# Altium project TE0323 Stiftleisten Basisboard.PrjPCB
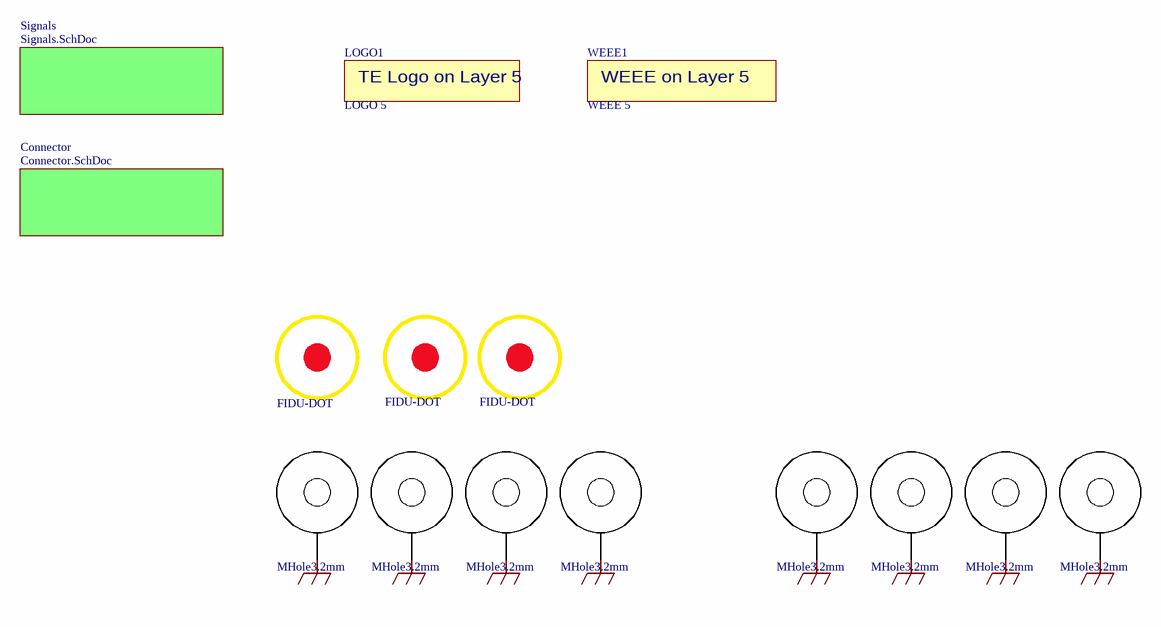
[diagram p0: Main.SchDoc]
3 sheets, 54 parts. Net scope: global (net labels, ports and power ports of the same name join across sheets).
Board file: TE0323.PcbDoc
Sheets:
  Main.SchDoc
    Connector = Connector.SchDoc
    Signals = Signals.SchDoc

## Sheet Main.SchDoc: Header Baseboard - TE0320 Module
size A4; Organization: Trenz Electronic GmbH; DocumentNumber: TE0323; Revision: 00; SheetNumber: 1; SheetTotal: 3; Date: 2008-07-08

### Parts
H1  MHole3.2mm  [MHole3_2mm]  (no BOM)
H2  MHole3.2mm  [MHole3_2mm]  (no BOM)
H3  MHole3.2mm  [MHole3_2mm]  (no BOM)
H4  MHole3.2mm  [MHole3_2mm]  (no BOM)
H5  MHole3.2mm  [MHole3_2mm]  (no BOM)
H6  MHole3.2mm  [MHole3_2mm]  (no BOM)
H7  MHole3.2mm  [MHole3_2mm]  (no BOM)
H8  MHole3.2mm  [MHole3_2mm]  (no BOM)
LOGO1  LOGO 5  [Logo 5]  (no BOM)
PM1  FIDU-DOT  [FIDU-DOT]
PM2  FIDU-DOT  [FIDU-DOT]
PM3  FIDU-DOT  [FIDU-DOT]
WEEE1  WEEE 5  [WEEE5_10_25mm]  (no BOM)

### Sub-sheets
Connector = Connector.SchDoc: no entries
Signals = Signals.SchDoc: no entries

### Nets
FGND: H1.1 H2.1 H3.1 H4.1 H5.1 H6.1 H7.1 H8.1

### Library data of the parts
H1-H8 = 22898: AN: 22898
LOGO1 = 22903: AN: 22903
PM1-PM3 = 22906: AN: 22906
WEEE1 = 23537: WEEE 5 (10.25mm); AN: 23537

## Sheet Connector.SchDoc: Header Baseboard - Headers
size A4; Organization: Trenz Electronic GmbH; DocumentNumber: TE0323; Revision: 00; SheetNumber: 3; SheetTotal: 3; Date: 2008-07-08
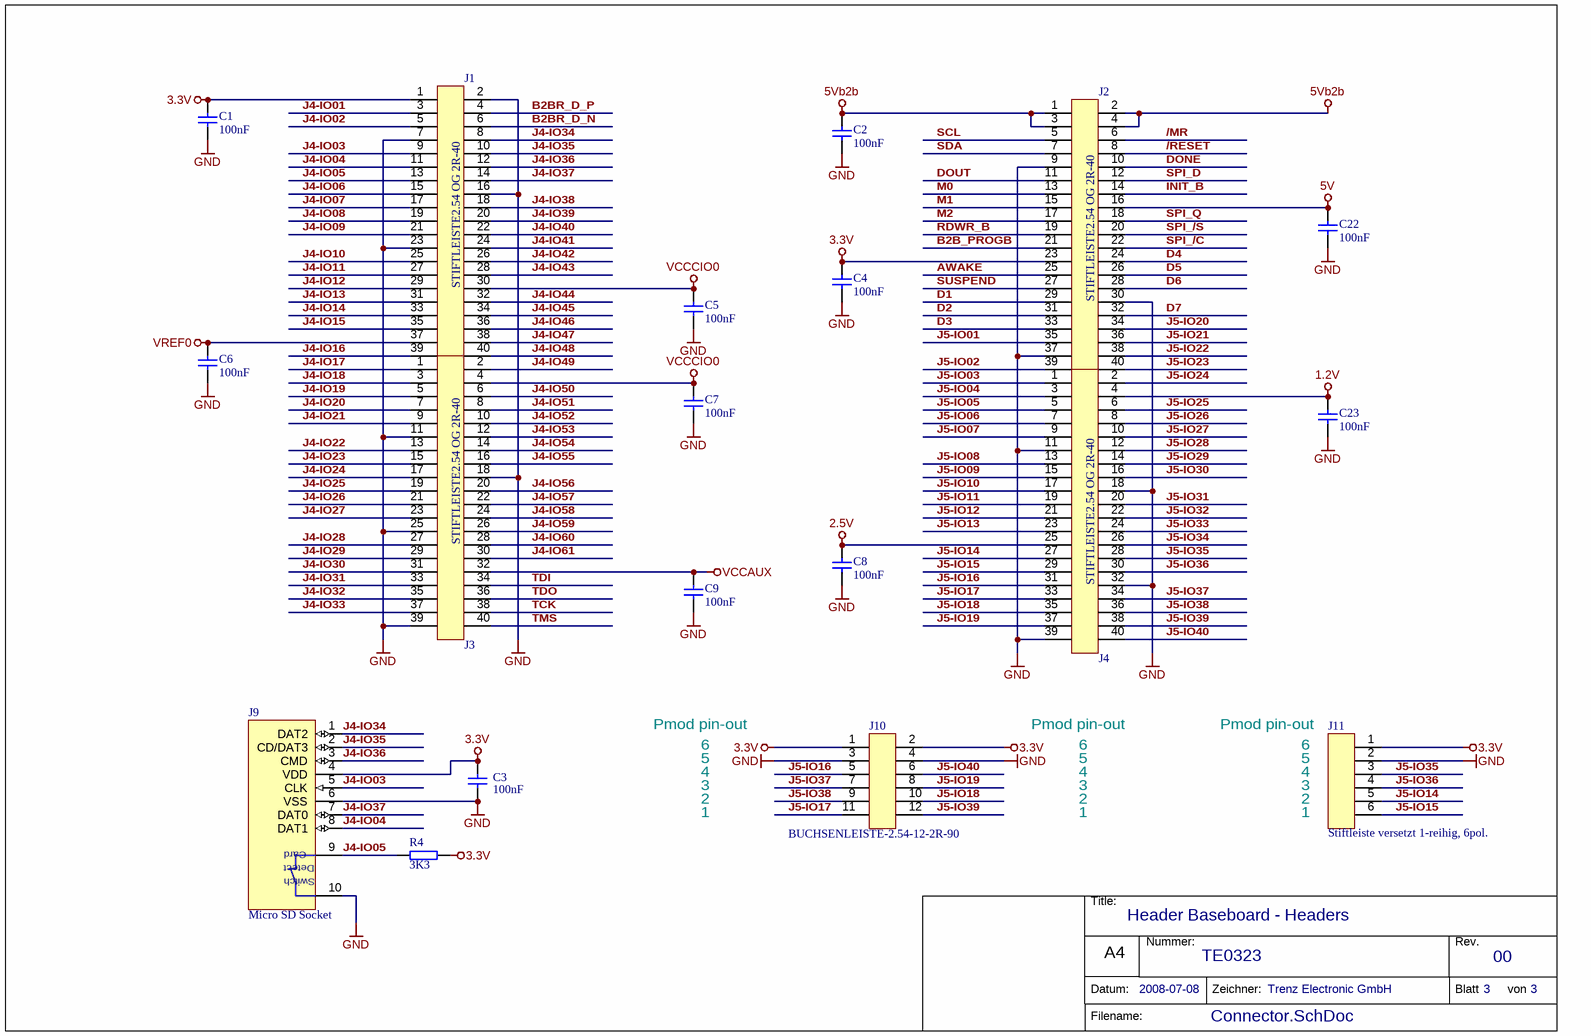
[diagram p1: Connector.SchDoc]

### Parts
C1  100nF  [CAPC1608N]
C2  100nF  [CAPC1608N]
C3  100nF  [CAPC1608N]
C4  100nF  [CAPC1608N]
C5  100nF  [CAPC1608N]
C6  100nF  [CAPC1608N]
C7  100nF  [CAPC1608N]
C8  100nF  [CAPC1608N]
C9  100nF  [CAPC1608N]
C22  100nF  [CAPC1608N]
C23  100nF  [CAPC1608N]
J1  STIFTLEISTE2.54 OG 2R-40  [STIFTLEISTE2_54 OG 2R-40]
J2  STIFTLEISTE2.54 OG 2R-40  [STIFTLEISTE2_54 OG 2R-40]
J3  STIFTLEISTE2.54 OG 2R-40  [STIFTLEISTE2_54 OG 2R-40]
J4  STIFTLEISTE2.54 OG 2R-40  [STIFTLEISTE2_54 OG 2R-40]
J9  Micro SD Socket  [112A-TXAR-R01]
J10  BUCHSENLEISTE-2.54-12-2R-90  [BUCHSENLEISTE-2.54-12-2R-90]
J11  Stiftleiste versetzt 1-reihig, 6pol.  [STIFTLEISTE2_54 OG 1R-6V]
R4  3K3  [RESC1609N]

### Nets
1.2V: C23.1 J4.4
2.5V: C8.1 J4.25
3.3V: C1.1 C3.1 C4.1 J1.1 J2.23 J9.4(VDD) J10.1 J10.2 J11.1 R4.2
5V: C22.1 J2.16
5Vb2b: C2.1 J2.1 J2.2 J2.3 J2.4
GND: C1.2 C2.2 C3.2 C4.2 C5.2 C6.2 C7.2 C8.2 C9.2 C22.2 C23.2 J1.2 J1.7 J1.16 J1.23 J2.9 J2.30 J2.37 J3.11 J3.18 J3.25 J3.39 J4.11 J4.18 J4.32 J4.39 J9.6(VSS) J9.10 J10.3 J10.4 J11.2
VCCAUX: C9.1 J3.32
VCCCIO0: C5.1 C7.1 J1.30 J3.4
VREF0: C6.1 J1.37
/MR: J2.6
/RESET: J2.8
AWAKE: J2.25
B2B_PROGB: J2.21
B2BR_D_N: J1.6
B2BR_D_P: J1.4
D1: J2.29
D2: J2.31
D3: J2.33
D4: J2.24
D5: J2.26
D6: J2.28
D7: J2.32
DONE: J2.10
DOUT: J2.11
INIT_B: J2.14
J4-IO01: J1.3
J4-IO02: J1.5
J4-IO03: J1.9 J9.5(CLK)
J4-IO04: J1.11 J9.8(DAT1)
J4-IO05: J1.13 J9.9 R4.1
J4-IO06: J1.15
J4-IO07: J1.17
J4-IO08: J1.19
J4-IO09: J1.21
J4-IO10: J1.25
J4-IO11: J1.27
J4-IO12: J1.29
J4-IO13: J1.31
J4-IO14: J1.33
J4-IO15: J1.35
J4-IO16: J1.39
J4-IO17: J3.1
J4-IO18: J3.3
J4-IO19: J3.5
J4-IO20: J3.7
J4-IO21: J3.9
J4-IO22: J3.13
J4-IO23: J3.15
J4-IO24: J3.17
J4-IO25: J3.19
J4-IO26: J3.21
J4-IO27: J3.23
J4-IO28: J3.27
J4-IO29: J3.29
J4-IO30: J3.31
J4-IO31: J3.33
J4-IO32: J3.35
J4-IO33: J3.37
J4-IO34: J1.8 J9.1(DAT2)
J4-IO35: J1.10 J9.2(CD/DAT3)
J4-IO36: J1.12 J9.3(CMD)
J4-IO37: J1.14 J9.7(DAT0)
J4-IO38: J1.18
J4-IO39: J1.20
J4-IO40: J1.22
J4-IO41: J1.24
J4-IO42: J1.26
J4-IO43: J1.28
J4-IO44: J1.32
J4-IO45: J1.34
J4-IO46: J1.36
J4-IO47: J1.38
J4-IO48: J1.40
J4-IO49: J3.2
J4-IO50: J3.6
J4-IO51: J3.8
J4-IO52: J3.10
J4-IO53: J3.12
J4-IO54: J3.14
J4-IO55: J3.16
J4-IO56: J3.20
J4-IO57: J3.22
J4-IO58: J3.24
J4-IO59: J3.26
J4-IO60: J3.28
J4-IO61: J3.30
J5-IO01: J2.35
J5-IO02: J2.39
J5-IO03: J4.1
J5-IO04: J4.3
J5-IO05: J4.5
J5-IO06: J4.7
J5-IO07: J4.9
J5-IO08: J4.13
J5-IO09: J4.15
J5-IO10: J4.17
J5-IO11: J4.19
J5-IO12: J4.21
J5-IO13: J4.23
J5-IO14: J4.27 J11.5
J5-IO15: J4.29 J11.6
J5-IO16: J4.31 J10.5
J5-IO17: J4.33 J10.11
J5-IO18: J4.35 J10.10
J5-IO19: J4.37 J10.8
J5-IO20: J2.34
J5-IO21: J2.36
J5-IO22: J2.38
J5-IO23: J2.40
J5-IO24: J4.2
J5-IO25: J4.6
J5-IO26: J4.8
J5-IO27: J4.10
J5-IO28: J4.12
J5-IO29: J4.14
J5-IO30: J4.16
J5-IO31: J4.20
J5-IO32: J4.22
J5-IO33: J4.24
J5-IO34: J4.26
J5-IO35: J4.28 J11.3
J5-IO36: J4.30 J11.4
J5-IO37: J4.34 J10.7
J5-IO38: J4.36 J10.9
J5-IO39: J4.38 J10.12
J5-IO40: J4.40 J10.6
M0: J2.13
M1: J2.15
M2: J2.17
RDWR_B: J2.19
SCL: J2.5
SDA: J2.7
SPI_/C: J2.22
SPI_/S: J2.20
SPI_D: J2.12
SPI_Q: J2.18
SUSPEND: J2.27
TCK: J3.38
TDI: J3.34
TDO: J3.36
TMS: J3.40

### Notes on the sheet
- Pmod pin-out
- 3
- 4
- 5
- 6
- (near J11) Pmod pin-out
- (near J11) 3
- (near J11) 4
- (near J11) 5
- (near J11) 6
- 1
- 2
- (near J11) 1
- (near J11) 2

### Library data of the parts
C1-C9 C22 C23 = 21382: KON 100nF 50V X7R SMD; AN: 21382; Value: 100n; Param 4: SMT
J1-J4 = 22320: Stiftleiste gerade 2-reihig, 40pol; AN: 22320; Trenz-Stock: Yes
J9 = 23193: AN: 23193; Param 4: SMT; Trenz-Stock: Yes
J10 = 23185: Buchsenleiste 2-reihig, 12pol 90°; AN: 23185; Trenz-Stock: Yes
J11 = 22911: AN: 22911; Trenz-Stock: Yes
R4 = 22433: WID SMD 3K3 1% 0,1W; AN: 22433; Value: 3.3K; Param 4: SMT

## Sheet Signals.SchDoc: Header Baseboard - TE0320 Module
size A4; Organization: Trenz Electronic GmbH; DocumentNumber: TE0323; Revision: 00; SheetNumber: 2; SheetTotal: 3; Date: 2008-07-08
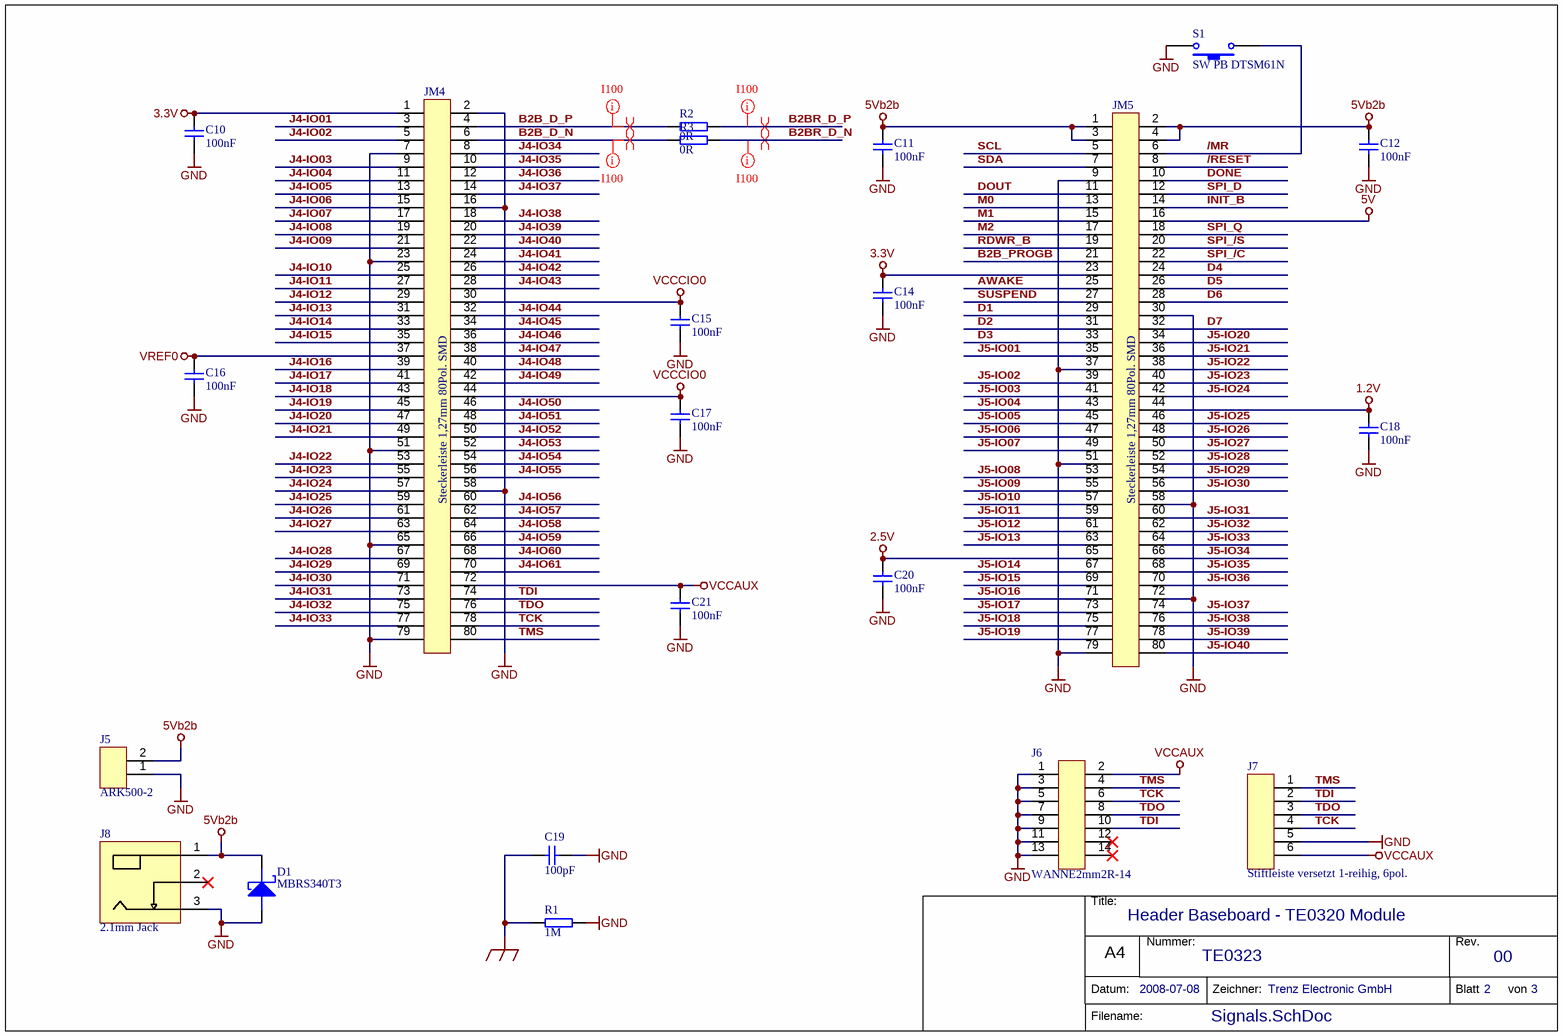
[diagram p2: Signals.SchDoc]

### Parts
C10  100nF  [CAPC1608N]
C11  100nF  [CAPC1608N]
C12  100nF  [CAPC1608N]
C14  100nF  [CAPC1608N]
C15  100nF  [CAPC1608N]
C16  100nF  [CAPC1608N]
C17  100nF  [CAPC1608N]
C18  100nF  [CAPC1608N]
C19  100pF  [CAPC3216N]
C20  100nF  [CAPC1608N]
C21  100nF  [CAPC1608N]
D1  MBRS340T3  [MBRS340T3]
J5  ARK500-2  [ARK500-2]
J6  WANNE2mm2R-14  [WANNE2mm2R-14]
J7  Stiftleiste versetzt 1-reihig, 6pol.  [STIFTLEISTE2_54 OG 1R-6V]
J8  2.1mm Jack  [WS-DC001]
JM4  Steckerleiste 1,27mm 80Pol. SMD  [6110-080-00-10]
JM5  Steckerleiste 1,27mm 80Pol. SMD  [6110-080-00-10]
R1  1M  [RESC3216N]
R2  0R  [RESC1609N]
R3  0R  [RESC1609N]
S1  SW PB DTSM61N  [DTSM61N]

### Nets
1.2V: C18.1 JM5.44
2.5V: C20.1 JM5.65
3.3V: C10.1 C14.1 JM4.1 JM5.23
5V: JM5.16
5Vb2b: C11.1 C12.1 D1.1(CATHODE) J5.2 J8.1 JM5.1 JM5.2 JM5.3 JM5.4
FGND: C19.1 R1.1
GND: C10.2 C11.2 C12.2 C14.2 C15.2 C16.2 C17.2 C18.2 C19.2 C20.2 C21.2 D1.2(ANODE) J5.1 J6.1 J6.3 J6.5 J6.7 J6.9 J6.11 J6.13 J7.5 J8.3 JM4.2 JM4.7 JM4.16 JM4.23 JM4.51 JM4.58 JM4.65 JM4.79 JM5.9 JM5.30 JM5.37 JM5.51 JM5.58 JM5.72 JM5.79 R1.2 S1.2
VCCAUX: C21.1 J6.2 J7.6 JM4.72
VCCCIO0: C15.1 C17.1 JM4.30 JM4.44
VREF0: C16.1 JM4.37
/MR: JM5.6 S1.1
/RESET: JM5.8
AWAKE: JM5.25
B2B_D_N: JM4.6 R3.1
B2B_D_P: JM4.4 R2.1
B2B_PROGB: JM5.21
B2BR_D_N: R3.2
B2BR_D_P: R2.2
D1: JM5.29
D2: JM5.31
D3: JM5.33
D4: JM5.24
D5: JM5.26
D6: JM5.28
D7: JM5.32
DONE: JM5.10
DOUT: JM5.11
INIT_B: JM5.14
J4-IO01: JM4.3
J4-IO02: JM4.5
J4-IO03: JM4.9
J4-IO04: JM4.11
J4-IO05: JM4.13
J4-IO06: JM4.15
J4-IO07: JM4.17
J4-IO08: JM4.19
J4-IO09: JM4.21
J4-IO10: JM4.25
J4-IO11: JM4.27
J4-IO12: JM4.29
J4-IO13: JM4.31
J4-IO14: JM4.33
J4-IO15: JM4.35
J4-IO16: JM4.39
J4-IO17: JM4.41
J4-IO18: JM4.43
J4-IO19: JM4.45
J4-IO20: JM4.47
J4-IO21: JM4.49
J4-IO22: JM4.53
J4-IO23: JM4.55
J4-IO24: JM4.57
J4-IO25: JM4.59
J4-IO26: JM4.61
J4-IO27: JM4.63
J4-IO28: JM4.67
J4-IO29: JM4.69
J4-IO30: JM4.71
J4-IO31: JM4.73
J4-IO32: JM4.75
J4-IO33: JM4.77
J4-IO34: JM4.8
J4-IO35: JM4.10
J4-IO36: JM4.12
J4-IO37: JM4.14
J4-IO38: JM4.18
J4-IO39: JM4.20
J4-IO40: JM4.22
J4-IO41: JM4.24
J4-IO42: JM4.26
J4-IO43: JM4.28
J4-IO44: JM4.32
J4-IO45: JM4.34
J4-IO46: JM4.36
J4-IO47: JM4.38
J4-IO48: JM4.40
J4-IO49: JM4.42
J4-IO50: JM4.46
J4-IO51: JM4.48
J4-IO52: JM4.50
J4-IO53: JM4.52
J4-IO54: JM4.54
J4-IO55: JM4.56
J4-IO56: JM4.60
J4-IO57: JM4.62
J4-IO58: JM4.64
J4-IO59: JM4.66
J4-IO60: JM4.68
J4-IO61: JM4.70
J5-IO01: JM5.35
J5-IO02: JM5.39
J5-IO03: JM5.41
J5-IO04: JM5.43
J5-IO05: JM5.45
J5-IO06: JM5.47
J5-IO07: JM5.49
J5-IO08: JM5.53
J5-IO09: JM5.55
J5-IO10: JM5.57
J5-IO11: JM5.59
J5-IO12: JM5.61
J5-IO13: JM5.63
J5-IO14: JM5.67
J5-IO15: JM5.69
J5-IO16: JM5.71
J5-IO17: JM5.73
J5-IO18: JM5.75
J5-IO19: JM5.77
J5-IO20: JM5.34
J5-IO21: JM5.36
J5-IO22: JM5.38
J5-IO23: JM5.40
J5-IO24: JM5.42
J5-IO25: JM5.46
J5-IO26: JM5.48
J5-IO27: JM5.50
J5-IO28: JM5.52
J5-IO29: JM5.54
J5-IO30: JM5.56
J5-IO31: JM5.60
J5-IO32: JM5.62
J5-IO33: JM5.64
J5-IO34: JM5.66
J5-IO35: JM5.68
J5-IO36: JM5.70
J5-IO37: JM5.74
J5-IO38: JM5.76
J5-IO39: JM5.78
J5-IO40: JM5.80
M0: JM5.13
M1: JM5.15
M2: JM5.17
RDWR_B: JM5.19
SCL: JM5.5
SDA: JM5.7
SPI_/C: JM5.22
SPI_/S: JM5.20
SPI_D: JM5.12
SPI_Q: JM5.18
SUSPEND: JM5.27
TCK: J6.6 J7.4 JM4.78
TDI: J6.10 J7.2 JM4.74
TDO: J6.8 J7.3 JM4.76
TMS: J6.4 J7.1 JM4.80

Not connected (* = marked no-connect by the designer): J6 12* 14*; J8 2*

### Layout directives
net class I100: B2B_D_N, B2B_D_P, B2BR_D_N, B2BR_D_P
differential pair: B2B_D_N, B2B_D_P, B2BR_D_N, B2BR_D_P

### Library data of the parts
C10-C12 C14-C18 C20 C21 = 21382: as C1 on sheet Connector
C19 = 22679: KON 100pF X7R; AN: 22679; Value: 100p
D1 = 22887: MBRS340T3 SMD; AN: 22887; Param 4: SMT
J5 = 20123: Schraubklemme LP 2 pol ARK500-2; AN: 20123; Trenz-Stock: Yes
J6 = 22744: Stiftleiste Wanne 14polig SMD; AN: 22744; Param 4: SMT; Trenz-Stock: Yes
J7 = 22911: AN: 22911; Trenz-Stock: Yes
J8 = 22832: STE 2,1mm Buchse; AN: 22832; Trenz-Stock: Yes
JM4 JM5 = 23749: STE B2B 80Pol. Steckerleiste 1,27mm SMD; AN: 23749; Param 4: SMT; Trenz-Stock: Yes
R1 = 22757: WID SMD 1M; AN: 22757; Param 4: SMT
R2 R3 = 21491: WID SMD 0R; AN: 21491; Value: 0; Param 4: SMT
S1 = 22596: Taster Miniatur Leiterplatte 1.6N; AN: 22596; Param 4: SMT; Trenz-Stock: Yes

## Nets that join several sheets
1.2V: Connector (C23.1 J4.4), Signals (C18.1 JM5.44)
2.5V: Connector (C8.1 J4.25), Signals (C20.1 JM5.65)
3.3V: Connector (10 pins), Signals (C10.1 C14.1 JM4.1 JM5.23)
5V: Connector (C22.1 J2.16), Signals (JM5.16)
5Vb2b: Connector (5 pins), Signals (9 pins)
FGND: Main (8 pins), Signals (C19.1 R1.1)
GND: Connector (31 pins), Signals (39 pins)
VCCAUX: Connector (C9.1 J3.32), Signals (C21.1 J6.2 J7.6 JM4.72)
VCCCIO0: Connector (C5.1 C7.1 J1.30 J3.4), Signals (C15.1 C17.1 JM4.30 JM4.44)
VREF0: Connector (C6.1 J1.37), Signals (C16.1 JM4.37)
/MR: Connector (J2.6), Signals (JM5.6 S1.1)
/RESET: Connector (J2.8), Signals (JM5.8)
AWAKE: Connector (J2.25), Signals (JM5.25)
B2B_PROGB: Connector (J2.21), Signals (JM5.21)
B2BR_D_N: Connector (J1.6), Signals (R3.2)
B2BR_D_P: Connector (J1.4), Signals (R2.2)
D1: Connector (J2.29), Signals (JM5.29)
D2: Connector (J2.31), Signals (JM5.31)
D3: Connector (J2.33), Signals (JM5.33)
D4: Connector (J2.24), Signals (JM5.24)
D5: Connector (J2.26), Signals (JM5.26)
D6: Connector (J2.28), Signals (JM5.28)
D7: Connector (J2.32), Signals (JM5.32)
DONE: Connector (J2.10), Signals (JM5.10)
DOUT: Connector (J2.11), Signals (JM5.11)
INIT_B: Connector (J2.14), Signals (JM5.14)
J4-IO01: Connector (J1.3), Signals (JM4.3)
J4-IO02: Connector (J1.5), Signals (JM4.5)
J4-IO03: Connector (J1.9 J9.5), Signals (JM4.9)
J4-IO04: Connector (J1.11 J9.8), Signals (JM4.11)
J4-IO05: Connector (J1.13 J9.9 R4.1), Signals (JM4.13)
J4-IO06: Connector (J1.15), Signals (JM4.15)
J4-IO07: Connector (J1.17), Signals (JM4.17)
J4-IO08: Connector (J1.19), Signals (JM4.19)
J4-IO09: Connector (J1.21), Signals (JM4.21)
J4-IO10: Connector (J1.25), Signals (JM4.25)
J4-IO11: Connector (J1.27), Signals (JM4.27)
J4-IO12: Connector (J1.29), Signals (JM4.29)
J4-IO13: Connector (J1.31), Signals (JM4.31)
J4-IO14: Connector (J1.33), Signals (JM4.33)
J4-IO15: Connector (J1.35), Signals (JM4.35)
J4-IO16: Connector (J1.39), Signals (JM4.39)
J4-IO17: Connector (J3.1), Signals (JM4.41)
J4-IO18: Connector (J3.3), Signals (JM4.43)
J4-IO19: Connector (J3.5), Signals (JM4.45)
J4-IO20: Connector (J3.7), Signals (JM4.47)
J4-IO21: Connector (J3.9), Signals (JM4.49)
J4-IO22: Connector (J3.13), Signals (JM4.53)
J4-IO23: Connector (J3.15), Signals (JM4.55)
J4-IO24: Connector (J3.17), Signals (JM4.57)
J4-IO25: Connector (J3.19), Signals (JM4.59)
J4-IO26: Connector (J3.21), Signals (JM4.61)
J4-IO27: Connector (J3.23), Signals (JM4.63)
J4-IO28: Connector (J3.27), Signals (JM4.67)
J4-IO29: Connector (J3.29), Signals (JM4.69)
J4-IO30: Connector (J3.31), Signals (JM4.71)
J4-IO31: Connector (J3.33), Signals (JM4.73)
J4-IO32: Connector (J3.35), Signals (JM4.75)
J4-IO33: Connector (J3.37), Signals (JM4.77)
J4-IO34: Connector (J1.8 J9.1), Signals (JM4.8)
J4-IO35: Connector (J1.10 J9.2), Signals (JM4.10)
J4-IO36: Connector (J1.12 J9.3), Signals (JM4.12)
J4-IO37: Connector (J1.14 J9.7), Signals (JM4.14)
J4-IO38: Connector (J1.18), Signals (JM4.18)
J4-IO39: Connector (J1.20), Signals (JM4.20)
J4-IO40: Connector (J1.22), Signals (JM4.22)
J4-IO41: Connector (J1.24), Signals (JM4.24)
J4-IO42: Connector (J1.26), Signals (JM4.26)
J4-IO43: Connector (J1.28), Signals (JM4.28)
J4-IO44: Connector (J1.32), Signals (JM4.32)
J4-IO45: Connector (J1.34), Signals (JM4.34)
J4-IO46: Connector (J1.36), Signals (JM4.36)
J4-IO47: Connector (J1.38), Signals (JM4.38)
J4-IO48: Connector (J1.40), Signals (JM4.40)
J4-IO49: Connector (J3.2), Signals (JM4.42)
J4-IO50: Connector (J3.6), Signals (JM4.46)
J4-IO51: Connector (J3.8), Signals (JM4.48)
J4-IO52: Connector (J3.10), Signals (JM4.50)
J4-IO53: Connector (J3.12), Signals (JM4.52)
J4-IO54: Connector (J3.14), Signals (JM4.54)
J4-IO55: Connector (J3.16), Signals (JM4.56)
J4-IO56: Connector (J3.20), Signals (JM4.60)
J4-IO57: Connector (J3.22), Signals (JM4.62)
J4-IO58: Connector (J3.24), Signals (JM4.64)
J4-IO59: Connector (J3.26), Signals (JM4.66)
J4-IO60: Connector (J3.28), Signals (JM4.68)
J4-IO61: Connector (J3.30), Signals (JM4.70)
J5-IO01: Connector (J2.35), Signals (JM5.35)
J5-IO02: Connector (J2.39), Signals (JM5.39)
J5-IO03: Connector (J4.1), Signals (JM5.41)
J5-IO04: Connector (J4.3), Signals (JM5.43)
J5-IO05: Connector (J4.5), Signals (JM5.45)
J5-IO06: Connector (J4.7), Signals (JM5.47)
J5-IO07: Connector (J4.9), Signals (JM5.49)
J5-IO08: Connector (J4.13), Signals (JM5.53)
J5-IO09: Connector (J4.15), Signals (JM5.55)
J5-IO10: Connector (J4.17), Signals (JM5.57)
J5-IO11: Connector (J4.19), Signals (JM5.59)
J5-IO12: Connector (J4.21), Signals (JM5.61)
J5-IO13: Connector (J4.23), Signals (JM5.63)
J5-IO14: Connector (J4.27 J11.5), Signals (JM5.67)
J5-IO15: Connector (J4.29 J11.6), Signals (JM5.69)
J5-IO16: Connector (J4.31 J10.5), Signals (JM5.71)
J5-IO17: Connector (J4.33 J10.11), Signals (JM5.73)
J5-IO18: Connector (J4.35 J10.10), Signals (JM5.75)
J5-IO19: Connector (J4.37 J10.8), Signals (JM5.77)
J5-IO20: Connector (J2.34), Signals (JM5.34)
J5-IO21: Connector (J2.36), Signals (JM5.36)
J5-IO22: Connector (J2.38), Signals (JM5.38)
J5-IO23: Connector (J2.40), Signals (JM5.40)
J5-IO24: Connector (J4.2), Signals (JM5.42)
J5-IO25: Connector (J4.6), Signals (JM5.46)
J5-IO26: Connector (J4.8), Signals (JM5.48)
J5-IO27: Connector (J4.10), Signals (JM5.50)
J5-IO28: Connector (J4.12), Signals (JM5.52)
J5-IO29: Connector (J4.14), Signals (JM5.54)
J5-IO30: Connector (J4.16), Signals (JM5.56)
J5-IO31: Connector (J4.20), Signals (JM5.60)
J5-IO32: Connector (J4.22), Signals (JM5.62)
J5-IO33: Connector (J4.24), Signals (JM5.64)
J5-IO34: Connector (J4.26), Signals (JM5.66)
J5-IO35: Connector (J4.28 J11.3), Signals (JM5.68)
J5-IO36: Connector (J4.30 J11.4), Signals (JM5.70)
J5-IO37: Connector (J4.34 J10.7), Signals (JM5.74)
J5-IO38: Connector (J4.36 J10.9), Signals (JM5.76)
J5-IO39: Connector (J4.38 J10.12), Signals (JM5.78)
J5-IO40: Connector (J4.40 J10.6), Signals (JM5.80)
M0: Connector (J2.13), Signals (JM5.13)
M1: Connector (J2.15), Signals (JM5.15)
M2: Connector (J2.17), Signals (JM5.17)
RDWR_B: Connector (J2.19), Signals (JM5.19)
SCL: Connector (J2.5), Signals (JM5.5)
SDA: Connector (J2.7), Signals (JM5.7)
SPI_/C: Connector (J2.22), Signals (JM5.22)
SPI_/S: Connector (J2.20), Signals (JM5.20)
SPI_D: Connector (J2.12), Signals (JM5.12)
SPI_Q: Connector (J2.18), Signals (JM5.18)
SUSPEND: Connector (J2.27), Signals (JM5.27)
TCK: Connector (J3.38), Signals (J6.6 J7.4 JM4.78)
TDI: Connector (J3.34), Signals (J6.10 J7.2 JM4.74)
TDO: Connector (J3.36), Signals (J6.8 J7.3 JM4.76)
TMS: Connector (J3.40), Signals (J6.4 J7.1 JM4.80)

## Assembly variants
P01: not fitted R2 R3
